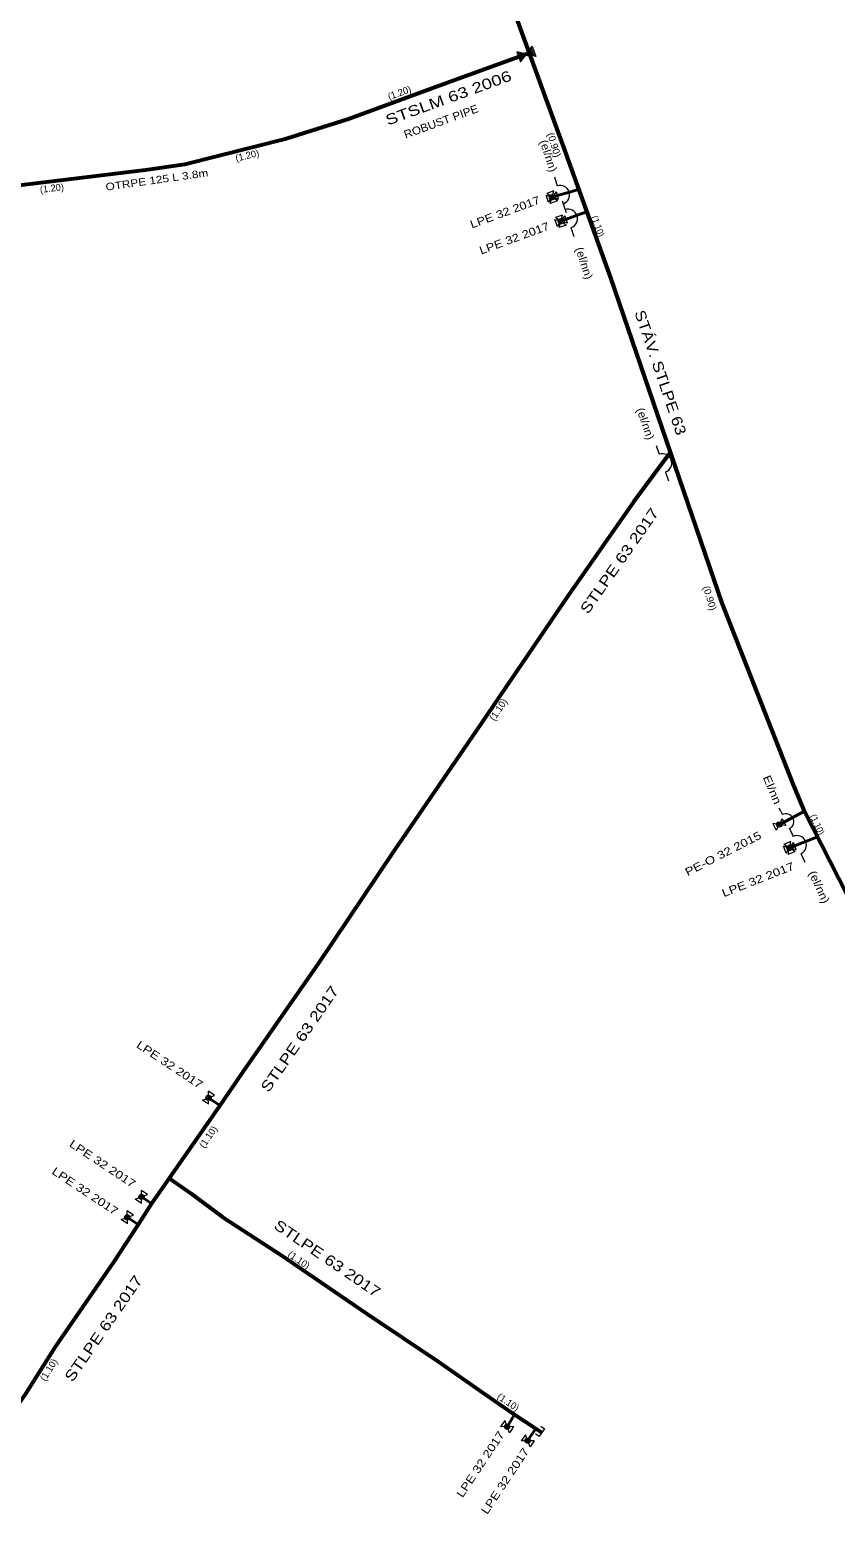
# Model space of a CAD drawing. Extents: x -648036 to -642998, y -1161549 to -1158141.
# Drawn here: x -646467.2 to -646391, y -1161361.9 to -1161219.3 of the extents above; entities that cross this region are included whole.
import ezdxf
from ezdxf.enums import TextEntityAlignment as Align

# ---------------------------------------------------------------- set-up
doc = ezdxf.new("R2010")
doc.units = 0
doc.header["$LTSCALE"] = 0.28
doc.linetypes.add('DASH_DOUBLE_DOT', pattern=[9.2, 5, -1.2, 0.3, -1.2, 0.3, -1.2])
for name, color, linetype, lineweight in [('12', 7, 'DASH_DOUBLE_DOT', 40), ('14', 7, 'Continuous', 13), ('15', 7, 'Continuous', 13), ('17', 7, 'Continuous', 13), ('19', 7, 'Continuous', 13), ('8', 7, 'Continuous', 53)]:
    doc.layers.add(name, color=color, linetype=linetype, lineweight=lineweight)
for name, color, linetype in [('20', 7, 'Continuous'), ('22', 7, 'Continuous'), ('24', 7, 'Continuous'), ('27', 7, 'Continuous'), ('28', 7, 'Continuous')]:
    doc.layers.add(name, color=color, linetype=linetype)

msp = doc.modelspace()

# ---------------------------------------------------------------- linework, layer by layer
at = {"layer": '12', "linetype": 'Continuous'}
for p, q in [((-646449.28, -1161321.03), (-646450.36, -1161320.31)), ((-646455.75, -1161330.31), (-646456.71, -1161329.68)), ((-646457.01, -1161332.29), (-646458.05, -1161331.61))]:
    msp.add_line(p, q, dxfattribs=at)
for points in [[(-646415.46, -1161234.42), (-646415.99, -1161234.58), (-646417.35, -1161234.98), (-646417.85, -1161235.13)], [(-646415.311, -1161234.375), (-646415.99, -1161234.58), (-646417.35, -1161234.98), (-646417.82, -1161235.12)], [(-646414.68, -1161236.55), (-646415.03, -1161236.68), (-646416.58, -1161237.25), (-646417.02, -1161237.41)], [(-646414.542, -1161236.499), (-646415.03, -1161236.68), (-646416.58, -1161237.25), (-646416.99, -1161237.4)], [(-646396.35, -1161294.46), (-646395.74, -1161294.14), (-646393.96, -1161293.21)], [(-646392.87, -1161295.7), (-646393.21, -1161295.83), (-646394.82, -1161296.46), (-646395.38, -1161296.68)], [(-646392.717, -1161295.641), (-646393.21, -1161295.83), (-646394.82, -1161296.46), (-646395.34, -1161296.66)], [(-646421.4, -1161350.26), (-646421.92, -1161351.12), (-646422.1, -1161351.42)], [(-646419.39, -1161351.59), (-646419.97, -1161352.48), (-646420.15, -1161352.75)]]:
    msp.add_lwpolyline(points, dxfattribs=at)
at = {"layer": '14'}
msp.add_line((-646452.61, -1161232.02), (-646456.34, -1161232.56), dxfattribs=at)
at = {"layer": '15'}
for p, q in [((-646420.752, -1161222.225), (-646421.047, -1161221.399)), ((-646420.657, -1161222.097), (-646420.893, -1161221.436)), ((-646420.569, -1161221.979), (-646420.749, -1161221.473)), ((-646420.471, -1161221.847), (-646420.591, -1161221.513)), ((-646420.373, -1161221.716), (-646420.431, -1161221.553)), ((-646420.119, -1161221.631), (-646420.18, -1161221.457)), ((-646419.964, -1161221.669), (-646420.086, -1161221.33)), ((-646419.846, -1161221.699), (-646420.013, -1161221.231)), ((-646419.709, -1161221.733), (-646419.929, -1161221.118)), ((-646419.548, -1161221.773), (-646419.83, -1161220.984)), ((-646417.632, -1161233.215), (-646417.356, -1161234.053)), ((-646417.632, -1161233.215), (-646417.356, -1161234.053)), ((-646417.683, -1161234.537), (-646418.353, -1161234.775)), ((-646418.2, -1161235.604), (-646417.44, -1161234.636)), ((-646418.017, -1161235.723), (-646417.683, -1161234.537)), ((-646417.236, -1161235.317), (-646417.44, -1161234.636)), ((-646418.404, -1161234.923), (-646417.236, -1161235.317)), ((-646418.2, -1161235.604), (-646418.404, -1161234.923)), ((-646417.347, -1161235.485), (-646418.353, -1161234.775)), ((-646417.347, -1161235.485), (-646418.017, -1161235.723)), ((-646416.892, -1161235.475), (-646416.616, -1161236.313)), ((-646416.892, -1161235.475), (-646416.616, -1161236.313)), ((-646416.801, -1161235.747), (-646416.528, -1161236.585)), ((-646416.801, -1161235.747), (-646416.528, -1161236.585)), ((-646417.585, -1161237.239), (-646416.395, -1161237.561)), ((-646417.34, -1161237.907), (-646417.585, -1161237.239)), ((-646416.853, -1161236.817), (-646417.523, -1161237.055)), ((-646416.517, -1161237.765), (-646417.523, -1161237.055)), ((-646417.34, -1161237.907), (-646416.64, -1161236.893)), ((-646417.187, -1161238.003), (-646416.853, -1161236.817)), ((-646416.395, -1161237.561), (-646416.64, -1161236.893)), ((-646416.517, -1161237.765), (-646417.187, -1161238.003)), ((-646416.061, -1161238.007), (-646415.788, -1161238.845)), ((-646416.061, -1161238.007), (-646415.788, -1161238.845)), ((-646408, -1161258.605), (-646407.711, -1161259.438)), ((-646407.127, -1161261.123), (-646406.84, -1161261.955)), ((-646396.39, -1161292.872), (-646396.056, -1161293.527)), ((-646396.961, -1161294.379), (-646396.631, -1161295.01)), ((-646395.738, -1161294.541), (-646396.961, -1161294.379)), ((-646396.069, -1161293.91), (-646396.631, -1161295.01)), ((-646396.069, -1161293.91), (-646395.738, -1161294.541)), ((-646395.396, -1161294.783), (-646395.034, -1161295.587)), ((-646395.396, -1161294.783), (-646395.034, -1161295.587)), ((-646395.383, -1161294.851), (-646395.051, -1161295.506)), ((-646395.938, -1161296.509), (-646394.742, -1161296.811)), ((-646395.681, -1161297.172), (-646395.938, -1161296.509)), ((-646395.246, -1161296.078), (-646395.902, -1161296.353)), ((-646394.858, -1161297.007), (-646395.902, -1161296.353)), ((-646395.681, -1161297.172), (-646394.999, -1161296.148)), ((-646395.514, -1161297.282), (-646395.246, -1161296.078)), ((-646394.858, -1161297.007), (-646395.514, -1161297.282)), ((-646394.742, -1161296.811), (-646394.999, -1161296.148)), ((-646394.304, -1161297.213), (-646393.944, -1161298.017)), ((-646394.304, -1161297.213), (-646393.944, -1161298.017)), ((-646450.938, -1161320.524), (-646449.782, -1161320.096)), ((-646449.782, -1161320.096), (-646450.369, -1161319.694)), ((-646450.351, -1161320.926), (-646450.369, -1161319.694)), ((-646450.351, -1161320.926), (-646450.938, -1161320.524)), ((-646457.288, -1161329.894), (-646456.132, -1161329.466)), ((-646456.701, -1161330.296), (-646457.288, -1161329.894)), ((-646456.132, -1161329.466), (-646456.719, -1161329.064)), ((-646456.701, -1161330.296), (-646456.719, -1161329.064)), ((-646458.628, -1161331.824), (-646457.472, -1161331.396)), ((-646457.472, -1161331.396), (-646458.059, -1161330.994)), ((-646458.041, -1161332.226), (-646458.059, -1161330.994)), ((-646458.041, -1161332.226), (-646458.628, -1161331.824)), ((-646422.313, -1161350.842), (-646422.716, -1161351.428)), ((-646421.484, -1161351.412), (-646422.716, -1161351.428)), ((-646421.887, -1161351.998), (-646422.313, -1161350.842)), ((-646421.484, -1161351.412), (-646421.887, -1161351.998)), ((-646418.926, -1161351.368), (-646418.562, -1161351.616)), ((-646420.363, -1161352.172), (-646420.766, -1161352.758)), ((-646419.534, -1161352.742), (-646420.766, -1161352.758)), ((-646419.937, -1161353.328), (-646420.363, -1161352.172)), ((-646419.534, -1161352.742), (-646419.937, -1161353.328)), ((-646419.059, -1161352.345), (-646419.423, -1161352.097))]:
    msp.add_line(p, q, dxfattribs=at)
msp.add_lwpolyline([(-646420.28, -1161221.59), (-646419.731, -1161220.852), (-646419.389, -1161221.813), (-646421.172, -1161221.367), (-646420.829, -1161222.328)], close=True, dxfattribs=at)
msp.add_lwpolyline([(-646418.562, -1161351.616), (-646418.81, -1161351.98), (-646419.059, -1161352.345)], dxfattribs=at)
for centre, radius, start, end in [((-646417.0795, -1161234.9), 0.8917, 289.41751, 107.98221), ((-646417.0795, -1161234.9), 0.8917, 289.41751, 107.98221), ((-646416.3395, -1161237.16), 0.8917, 289.41751, 107.98221), ((-646416.3395, -1161237.16), 0.8917, 289.41751, 107.98221), ((-646407.4195, -1161260.28), 0.8917, 290.3912, 108.95591), ((-646395.7203, -1161294.189), 0.7431, 298.21351, 116.77822), ((-646394.6695, -1161296.3999), 0.8917, 295.47361, 114.03832), ((-646394.6695, -1161296.3999), 0.8917, 295.47361, 114.03832)]:
    msp.add_arc(centre, radius, start, end, dxfattribs=at)
at = {"layer": '17'}
for centre, radius in [((-646417.85, -1161235.13), 0.25), ((-646417.82, -1161235.12), 0.25), ((-646417.85, -1161235.13), 0.17), ((-646417.82, -1161235.12), 0.17), ((-646417.85, -1161235.13), 0.09), ((-646417.82, -1161235.12), 0.09), ((-646417.02, -1161237.41), 0.25), ((-646416.99, -1161237.4), 0.25), ((-646417.02, -1161237.41), 0.17), ((-646416.99, -1161237.4), 0.17), ((-646417.02, -1161237.41), 0.09), ((-646416.99, -1161237.4), 0.09), ((-646395.38, -1161296.68), 0.25), ((-646395.34, -1161296.66), 0.25), ((-646395.38, -1161296.68), 0.17), ((-646395.34, -1161296.66), 0.17), ((-646395.38, -1161296.68), 0.09), ((-646395.34, -1161296.66), 0.09), ((-646450.36, -1161320.31), 0.25), ((-646450.36, -1161320.31), 0.17), ((-646450.36, -1161320.31), 0.09), ((-646456.71, -1161329.68), 0.25), ((-646456.71, -1161329.68), 0.17), ((-646456.71, -1161329.68), 0.09), ((-646458.05, -1161331.61), 0.25), ((-646458.05, -1161331.61), 0.17), ((-646458.05, -1161331.61), 0.09), ((-646422.1, -1161351.42), 0.25), ((-646422.1, -1161351.42), 0.17), ((-646422.1, -1161351.42), 0.09), ((-646420.15, -1161352.75), 0.25), ((-646420.15, -1161352.75), 0.17), ((-646420.15, -1161352.75), 0.09)]:
    msp.add_circle(centre, radius, dxfattribs=at)
at = {"layer": '19'}
for radius in [0.25, 0.17, 0.09]:
    msp.add_circle((-646396.35, -1161294.46), radius, dxfattribs=at)
at = {"layer": '8'}
msp.add_line((-646420.28, -1161221.59), (-646420, -1161221.49), dxfattribs=at)
for points in [[(-646420, -1161221.49), (-646430.2, -1161193.49), (-646432.114, -1161187.278)], [(-646420.28, -1161221.59), (-646428.53, -1161224.61), (-646437.12, -1161227.75), (-646443.11, -1161229.65), (-646452.61, -1161232.02), (-646456.34, -1161232.56), (-646468.83, -1161234.09), (-646472.44, -1161234.63)], [(-646379.06, -1161319.19), (-646388.27, -1161304.34), (-646393.96, -1161293.21), (-646394.99, -1161290.71), (-646401.75, -1161273.53), (-646412.28, -1161242.74), (-646416.56, -1161230.93), (-646420, -1161221.49)], [(-646406.63, -1161259.26), (-646407.14, -1161259.9), (-646407.78, -1161260.75), (-646410.1, -1161263.91), (-646416.34, -1161272.8), (-646425.02, -1161285.59), (-646432.79, -1161296.92), (-646439.95, -1161307.59), (-646447.11, -1161317.84), (-646449.28, -1161321.03), (-646454.09, -1161327.92)], [(-646454.09, -1161327.92), (-646455.75, -1161330.31), (-646457.01, -1161332.29), (-646459.36, -1161335.87), (-646464.86, -1161343.85), (-646467.73, -1161348.4), (-646472.48, -1161355), (-646477.62, -1161361.93), (-646481.83, -1161360.01), (-646484.28, -1161358.8), (-646486.89, -1161357.46), (-646489.05, -1161356.35), (-646496.41, -1161352.73), (-646504.05, -1161348.91), (-646512.58, -1161344.74), (-646520.67, -1161340.71), (-646529.61, -1161336.32), (-646537.52, -1161332.28), (-646543.6, -1161329.4), (-646544.06, -1161329.16), (-646545.63, -1161328.33), (-646546.46, -1161327.88), (-646548.5, -1161326.72)], [(-646454.09, -1161327.92), (-646451.99, -1161329.36), (-646449, -1161331.6), (-646443.41, -1161335.24), (-646435.34, -1161340.74), (-646428.65, -1161345.23), (-646423.34, -1161348.95), (-646421.4, -1161350.26), (-646419.39, -1161351.59), (-646418.81, -1161351.98)]]:
    msp.add_lwpolyline(points, dxfattribs=at)

# ---------------------------------------------------------------- texts
at = {"layer": '20', "width": 1.3}
msp.add_text('STSLM 63 2006', height=1, rotation=20.054, dxfattribs=at).set_placement((-646427.4839, -1161226.2037), align=Align.CENTER)
at = {"layer": '20'}
for s, rotation, width, p in [('STÁV. STLPE 63', 288.881, 1.2, (-646410.071, -1161246.007)), ('STLPE 63 2017', 54.936, 1.25, (-646414.456, -1161274.637)), ('STLPE 63 2017', 55.299, 1.25, (-646444.68, -1161319.879)), ('STLPE 63 2017', 325.724, 1.25, (-646444.276, -1161332.595)), ('STLPE 63 2017', 55.424, 1.25, (-646463.237, -1161347.27))]:
    msp.add_text(s, height=1, rotation=rotation, dxfattribs=dict(at, width=width)).set_placement(p)
at = {"layer": '22'}
for s, rotation, width, p in [('ROBUST PIPE', 20.054, 1.1, (-646428.2256, -1161228.3171)), ('PE-O 32 2015', 27.116, 1.25, (-646401.4899, -1161297.5486))]:
    msp.add_text(s, height=0.75, rotation=rotation, dxfattribs=dict(at, width=width)).set_placement(p, align=Align.CENTER)
for rotation, width, p in [(20.148, 1.2, (-646425.44, -1161238.09)), (20.148, 1.2, (-646425.44, -1161238.09)), (20.148, 1.2, (-646424.56, -1161240.56)), (20.148, 1.2, (-646424.56, -1161240.56)), (21.458, 1.25, (-646401.6, -1161301.34)), (21.458, 1.25, (-646401.6, -1161301.34)), (326.378, 1.25, (-646457.26, -1161315.48)), (326.378, 1.25, (-646463.61, -1161324.85)), (326.378, 1.25, (-646465.27, -1161327.44)), (56.378, 1.25, (-646426.321, -1161358.193)), (56.378, 1.25, (-646423.994, -1161359.777))]:
    msp.add_text('LPE 32 2017', height=0.75, rotation=rotation, dxfattribs=dict(at, width=width)).set_placement(p)
at = {"layer": '24', "width": 1.2}
msp.add_text('OTRPE 125 L 3.8m', height=0.7, rotation=8.021, dxfattribs=at).set_placement((-646455.2003, -1161233.8317), align=Align.CENTER)
at = {"layer": '27'}
for rotation, p in [(20.054, (-646432.1799, -1161225.5574)), (13.751, (-646446.6198, -1161231.4997)), (6.875, (-646465.1484, -1161234.5941))]:
    msp.add_text('(1.20)', height=0.65, rotation=rotation, dxfattribs=at).set_placement(p, align=Align.CENTER)
at = {"layer": '27', "width": 1.05}
for rotation, p in [(287.625, (-646417.9603, -1161230.2791)), (287.052, (-646403.2319, -1161273.1452))]:
    msp.add_text('(0.90)', height=0.65, rotation=rotation, dxfattribs=at).set_placement(p, align=Align.CENTER)
at = {"layer": '27', "width": 0.9}
for rotation, p in [(290.014, (-646414.17, -1161237.024)), (290.014, (-646414.17, -1161237.024)), (294.444, (-646393.477, -1161293.67)), (294.444, (-646393.477, -1161293.67))]:
    msp.add_text('(1.10)', height=0.65, rotation=rotation, dxfattribs=at).set_placement(p)
at = {"layer": '27'}
for rotation, p in [(55.836, (-646423.301, -1161284.709)), (55.299, (-646450.77, -1161325.12)), (325.724, (-646442.929, -1161335.276)), (57.758, (-646465.812, -1161347.172)), (325.971, (-646423.119, -1161348.725))]:
    msp.add_text('(1.10)', height=0.65, rotation=rotation, dxfattribs=at).set_placement(p)
at = {"layer": '28'}
for rotation, width, p in [(288.13, 1.1, (-646418.5462, -1161231.3348)), (288.13, 1.1, (-646418.5462, -1161231.3348)), (288.13, 1.1, (-646415.1682, -1161241.4778)), (288.13, 1.1, (-646415.1682, -1161241.4778)), (289.104, 1.1, (-646409.3639, -1161256.6648)), (294.186, 1.15, (-646392.918, -1161300.5224)), (294.186, 1.15, (-646392.918, -1161300.5224))]:
    msp.add_text('(el/nn)', height=0.75, rotation=rotation, dxfattribs=dict(at, width=width)).set_placement(p, align=Align.CENTER)
at = {"layer": '28', "width": 1.25}
msp.add_text('El/nn', height=0.75, rotation=292.963, dxfattribs=at).set_placement((-646397.913, -1161289.997))

doc.saveas('drawing.dxf')
